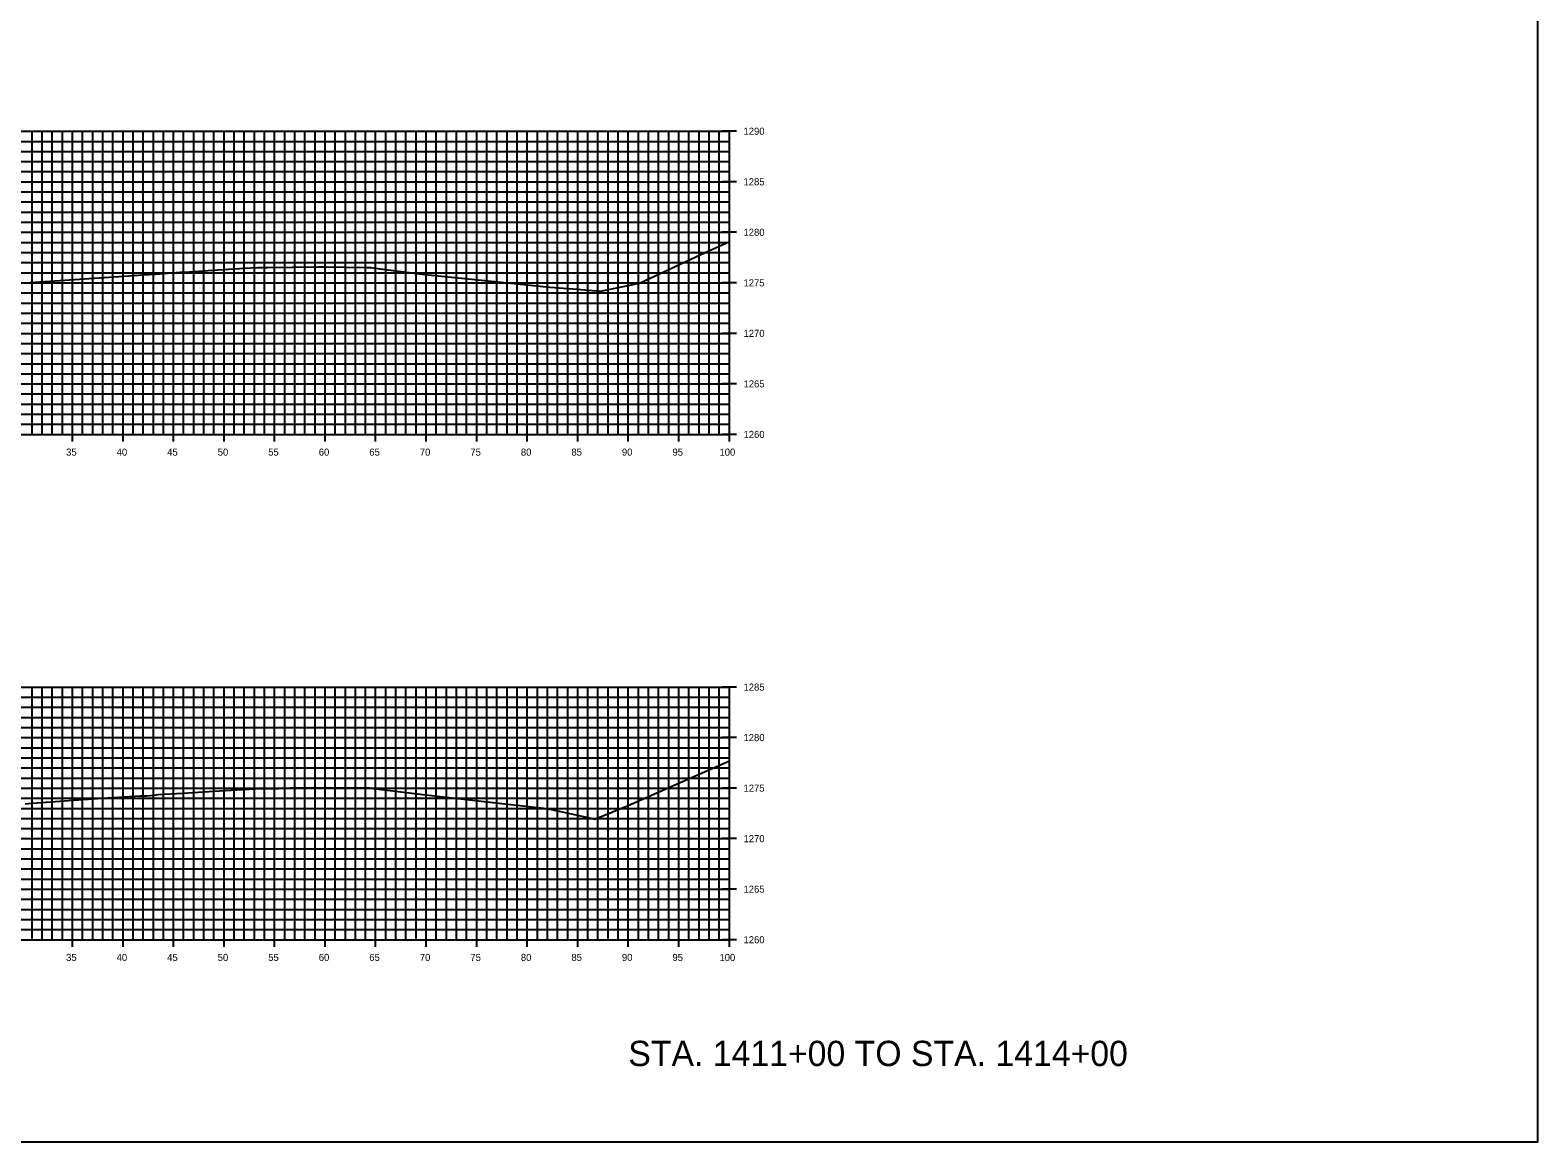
# Model space of a CAD drawing. Extents: x 674939 to 678919, y 750652 to 765176.
# Drawn here: x 678769.3 to 678918.5, y 757132.6 to 757242.6 of the extents above; entities that cross this region are included whole.
import ezdxf

# ---------------------------------------------------------------- set-up
doc = ezdxf.new("R2010")
doc.units = 0
for name, color, linetype in [('Level 10', 7, 'Continuous'), ('Level 20', 7, 'Continuous'), ('Level 21', 7, 'Continuous'), ('Level 4', 7, 'Continuous'), ('Level 8', 7, 'Continuous'), ('Level 9', 7, 'Continuous')]:
    doc.layers.add(name, color=color, linetype=linetype)

msp = doc.modelspace()

# ---------------------------------------------------------------- linework, layer by layer
at = {"layer": 'Level 10'}
for points in [[(678768.39, 757217.5), (678770.77, 757217.69), (678771.79, 757217.76), (678780.57, 757218.34), (678781.69, 757218.41), (678781.76, 757218.41), (678782.2, 757218.45), (678784.16, 757218.59), (678785.11, 757218.65), (678787.89, 757218.83), (678791.15, 757219.02), (678791.88, 757219.06), (678792.07, 757219.07), (678792.09, 757219.07), (678792.84, 757219.08), (678797.78, 757219.13), (678798.55, 757219.13), (678802.68, 757219.07), (678803.06, 757219.06), (678803.09, 757219.06), (678803.99, 757218.95), (678808.4, 757218.38), (678813.99, 757217.81), (678820.78, 757217.13), (678823.05, 757216.95), (678825.79, 757216.72), (678828.52, 757217.29), (678829.64, 757217.51), (678836.13, 757220.55), (678838.53, 757221.65)], [(678768.86, 757166.01), (678769.56, 757166.07), (678773.17, 757166.32), (678775.08, 757166.45), (678777, 757166.58), (678780.24, 757166.79), (678780.64, 757166.8), (678780.88, 757166.79), (678781.6, 757166.87), (678782, 757166.91), (678784.4, 757167.06), (678788.12, 757167.29), (678789.78, 757167.39), (678792.17, 757167.51), (678792.26, 757167.51), (678792.4, 757167.52), (678792.64, 757167.5), (678793.24, 757167.49), (678793.96, 757167.53), (678795.04, 757167.57), (678796.64, 757167.59), (678799.41, 757167.59), (678801, 757167.58), (678802.92, 757167.57), (678803, 757167.56), (678804.96, 757167.32), (678807.63, 757167), (678815.42, 757166.1), (678820.46, 757165.54), (678824.99, 757164.54), (678825.11, 757164.52), (678825.21, 757164.49), (678825.27, 757164.52), (678828.51, 757165.82), (678833.07, 757167.84), (678838.53, 757170.26)]]:
    msp.add_lwpolyline(points, dxfattribs=at)
at = {"layer": 'Level 20'}
for p, q in [((678638.53, 757232.55), (678838.53, 757232.55)), ((678769.53, 757202.55), (678769.53, 757232.55)), ((678770.53, 757202.55), (678770.53, 757232.55)), ((678771.53, 757202.55), (678771.53, 757232.55)), ((678772.53, 757202.55), (678772.53, 757232.55)), ((678773.53, 757202.55), (678773.53, 757232.55)), ((678774.53, 757202.55), (678774.53, 757232.55)), ((678775.53, 757202.55), (678775.53, 757232.55)), ((678776.53, 757202.55), (678776.53, 757232.55)), ((678777.53, 757202.55), (678777.53, 757232.55)), ((678778.53, 757202.55), (678778.53, 757232.55)), ((678779.53, 757202.55), (678779.53, 757232.55)), ((678780.53, 757202.55), (678780.53, 757232.55)), ((678781.53, 757202.55), (678781.53, 757232.55)), ((678782.53, 757202.55), (678782.53, 757232.55)), ((678783.53, 757202.55), (678783.53, 757232.55)), ((678784.53, 757202.55), (678784.53, 757232.55)), ((678785.53, 757202.55), (678785.53, 757232.55)), ((678786.53, 757202.55), (678786.53, 757232.55)), ((678787.53, 757202.55), (678787.53, 757232.55)), ((678788.53, 757202.55), (678788.53, 757232.55)), ((678789.53, 757202.55), (678789.53, 757232.55)), ((678790.53, 757202.55), (678790.53, 757232.55)), ((678791.53, 757202.55), (678791.53, 757232.55)), ((678792.53, 757202.55), (678792.53, 757232.55)), ((678793.53, 757202.55), (678793.53, 757232.55)), ((678794.53, 757202.55), (678794.53, 757232.55)), ((678795.53, 757202.55), (678795.53, 757232.55)), ((678796.53, 757202.55), (678796.53, 757232.55)), ((678797.53, 757202.55), (678797.53, 757232.55)), ((678798.53, 757202.55), (678798.53, 757232.55)), ((678799.53, 757202.55), (678799.53, 757232.55)), ((678800.53, 757202.55), (678800.53, 757232.55)), ((678801.53, 757202.55), (678801.53, 757232.55)), ((678802.53, 757202.55), (678802.53, 757232.55)), ((678803.53, 757202.55), (678803.53, 757232.55)), ((678804.53, 757202.55), (678804.53, 757232.55)), ((678805.53, 757202.55), (678805.53, 757232.55)), ((678806.53, 757202.55), (678806.53, 757232.55)), ((678807.53, 757202.55), (678807.53, 757232.55)), ((678808.53, 757202.55), (678808.53, 757232.55)), ((678809.53, 757202.55), (678809.53, 757232.55)), ((678810.53, 757202.55), (678810.53, 757232.55)), ((678811.53, 757202.55), (678811.53, 757232.55)), ((678812.53, 757202.55), (678812.53, 757232.55)), ((678813.53, 757202.55), (678813.53, 757232.55)), ((678814.53, 757202.55), (678814.53, 757232.55)), ((678815.53, 757202.55), (678815.53, 757232.55)), ((678816.53, 757202.55), (678816.53, 757232.55)), ((678817.53, 757202.55), (678817.53, 757232.55)), ((678818.53, 757202.55), (678818.53, 757232.55)), ((678819.53, 757202.55), (678819.53, 757232.55)), ((678820.53, 757202.55), (678820.53, 757232.55)), ((678821.53, 757202.55), (678821.53, 757232.55)), ((678822.53, 757202.55), (678822.53, 757232.55)), ((678823.53, 757202.55), (678823.53, 757232.55)), ((678824.53, 757202.55), (678824.53, 757232.55)), ((678825.53, 757202.55), (678825.53, 757232.55)), ((678826.53, 757202.55), (678826.53, 757232.55)), ((678827.53, 757202.55), (678827.53, 757232.55)), ((678828.53, 757202.55), (678828.53, 757232.55)), ((678829.53, 757202.55), (678829.53, 757232.55)), ((678830.53, 757202.55), (678830.53, 757232.55)), ((678831.53, 757202.55), (678831.53, 757232.55)), ((678832.53, 757202.55), (678832.53, 757232.55)), ((678833.53, 757202.55), (678833.53, 757232.55)), ((678834.53, 757202.55), (678834.53, 757232.55)), ((678835.53, 757202.55), (678835.53, 757232.55)), ((678836.53, 757202.55), (678836.53, 757232.55)), ((678837.53, 757202.55), (678837.53, 757232.55)), ((678838.53, 757202.55), (678838.53, 757232.55)), ((678638.53, 757231.55), (678838.53, 757231.55)), ((678638.53, 757230.55), (678838.53, 757230.55)), ((678638.53, 757229.55), (678838.53, 757229.55)), ((678638.53, 757228.55), (678838.53, 757228.55)), ((678638.53, 757227.55), (678838.53, 757227.55)), ((678638.53, 757226.55), (678838.53, 757226.55)), ((678638.53, 757225.55), (678838.53, 757225.55)), ((678638.53, 757224.55), (678838.53, 757224.55)), ((678638.53, 757223.55), (678838.53, 757223.55)), ((678638.53, 757222.55), (678838.53, 757222.55)), ((678638.53, 757221.55), (678838.53, 757221.55)), ((678638.53, 757220.55), (678838.53, 757220.55)), ((678638.53, 757219.55), (678838.53, 757219.55)), ((678638.53, 757218.55), (678838.53, 757218.55)), ((678638.53, 757217.55), (678838.53, 757217.55)), ((678638.53, 757216.55), (678838.53, 757216.55)), ((678638.53, 757215.55), (678838.53, 757215.55)), ((678638.53, 757214.55), (678838.53, 757214.55)), ((678638.53, 757213.55), (678838.53, 757213.55)), ((678638.53, 757212.55), (678838.53, 757212.55)), ((678638.53, 757211.55), (678838.53, 757211.55)), ((678638.53, 757210.55), (678838.53, 757210.55)), ((678638.53, 757209.55), (678838.53, 757209.55)), ((678638.53, 757208.55), (678838.53, 757208.55)), ((678638.53, 757207.55), (678838.53, 757207.55)), ((678638.53, 757206.55), (678838.53, 757206.55)), ((678638.53, 757205.55), (678838.53, 757205.55)), ((678638.53, 757204.55), (678838.53, 757204.55)), ((678638.53, 757203.55), (678838.53, 757203.55)), ((678638.53, 757202.55), (678838.53, 757202.55)), ((678638.53, 757177.55), (678838.53, 757177.55)), ((678769.53, 757152.55), (678769.53, 757177.55)), ((678770.53, 757152.55), (678770.53, 757177.55)), ((678771.53, 757152.55), (678771.53, 757177.55)), ((678772.53, 757152.55), (678772.53, 757177.55)), ((678773.53, 757152.55), (678773.53, 757177.55)), ((678774.53, 757152.55), (678774.53, 757177.55)), ((678775.53, 757152.55), (678775.53, 757177.55)), ((678776.53, 757152.55), (678776.53, 757177.55)), ((678777.53, 757152.55), (678777.53, 757177.55)), ((678778.53, 757152.55), (678778.53, 757177.55)), ((678779.53, 757152.55), (678779.53, 757177.55)), ((678780.53, 757152.55), (678780.53, 757177.55)), ((678781.53, 757152.55), (678781.53, 757177.55)), ((678782.53, 757152.55), (678782.53, 757177.55)), ((678783.53, 757152.55), (678783.53, 757177.55)), ((678784.53, 757152.55), (678784.53, 757177.55)), ((678785.53, 757152.55), (678785.53, 757177.55)), ((678786.53, 757152.55), (678786.53, 757177.55)), ((678787.53, 757152.55), (678787.53, 757177.55)), ((678788.53, 757152.55), (678788.53, 757177.55)), ((678789.53, 757152.55), (678789.53, 757177.55)), ((678790.53, 757152.55), (678790.53, 757177.55)), ((678791.53, 757152.55), (678791.53, 757177.55)), ((678792.53, 757152.55), (678792.53, 757177.55)), ((678793.53, 757152.55), (678793.53, 757177.55)), ((678794.53, 757152.55), (678794.53, 757177.55)), ((678795.53, 757152.55), (678795.53, 757177.55)), ((678796.53, 757152.55), (678796.53, 757177.55)), ((678797.53, 757152.55), (678797.53, 757177.55)), ((678798.53, 757152.55), (678798.53, 757177.55)), ((678799.53, 757152.55), (678799.53, 757177.55)), ((678800.53, 757152.55), (678800.53, 757177.55)), ((678801.53, 757152.55), (678801.53, 757177.55)), ((678802.53, 757152.55), (678802.53, 757177.55)), ((678803.53, 757152.55), (678803.53, 757177.55)), ((678804.53, 757152.55), (678804.53, 757177.55)), ((678805.53, 757152.55), (678805.53, 757177.55)), ((678806.53, 757152.55), (678806.53, 757177.55)), ((678807.53, 757152.55), (678807.53, 757177.55)), ((678808.53, 757152.55), (678808.53, 757177.55)), ((678809.53, 757152.55), (678809.53, 757177.55)), ((678810.53, 757152.55), (678810.53, 757177.55)), ((678811.53, 757152.55), (678811.53, 757177.55)), ((678812.53, 757152.55), (678812.53, 757177.55)), ((678813.53, 757152.55), (678813.53, 757177.55)), ((678814.53, 757152.55), (678814.53, 757177.55)), ((678815.53, 757152.55), (678815.53, 757177.55)), ((678816.53, 757152.55), (678816.53, 757177.55)), ((678817.53, 757152.55), (678817.53, 757177.55)), ((678818.53, 757152.55), (678818.53, 757177.55)), ((678819.53, 757152.55), (678819.53, 757177.55)), ((678820.53, 757152.55), (678820.53, 757177.55)), ((678821.53, 757152.55), (678821.53, 757177.55)), ((678822.53, 757152.55), (678822.53, 757177.55)), ((678823.53, 757152.55), (678823.53, 757177.55)), ((678824.53, 757152.55), (678824.53, 757177.55)), ((678825.53, 757152.55), (678825.53, 757177.55)), ((678826.53, 757152.55), (678826.53, 757177.55)), ((678827.53, 757152.55), (678827.53, 757177.55)), ((678828.53, 757152.55), (678828.53, 757177.55)), ((678829.53, 757152.55), (678829.53, 757177.55)), ((678830.53, 757152.55), (678830.53, 757177.55)), ((678831.53, 757152.55), (678831.53, 757177.55)), ((678832.53, 757152.55), (678832.53, 757177.55)), ((678833.53, 757152.55), (678833.53, 757177.55)), ((678834.53, 757152.55), (678834.53, 757177.55)), ((678835.53, 757152.55), (678835.53, 757177.55)), ((678836.53, 757152.55), (678836.53, 757177.55)), ((678837.53, 757152.55), (678837.53, 757177.55)), ((678838.53, 757152.55), (678838.53, 757177.55)), ((678638.53, 757176.55), (678838.53, 757176.55)), ((678638.53, 757175.55), (678838.53, 757175.55)), ((678638.53, 757174.55), (678838.53, 757174.55)), ((678638.53, 757173.55), (678838.53, 757173.55)), ((678638.53, 757172.55), (678838.53, 757172.55)), ((678638.53, 757171.55), (678838.53, 757171.55)), ((678638.53, 757170.55), (678838.53, 757170.55)), ((678638.53, 757169.55), (678838.53, 757169.55)), ((678638.53, 757168.55), (678838.53, 757168.55)), ((678638.53, 757167.55), (678838.53, 757167.55)), ((678638.53, 757166.55), (678838.53, 757166.55)), ((678638.53, 757165.55), (678838.53, 757165.55)), ((678638.53, 757164.55), (678838.53, 757164.55)), ((678638.53, 757163.55), (678838.53, 757163.55)), ((678638.53, 757162.55), (678838.53, 757162.55)), ((678638.53, 757161.55), (678838.53, 757161.55)), ((678638.53, 757160.55), (678838.53, 757160.55)), ((678638.53, 757159.55), (678838.53, 757159.55)), ((678638.53, 757158.55), (678838.53, 757158.55)), ((678638.53, 757157.55), (678838.53, 757157.55)), ((678638.53, 757156.55), (678838.53, 757156.55)), ((678638.53, 757155.55), (678838.53, 757155.55)), ((678638.53, 757154.55), (678838.53, 757154.55)), ((678638.53, 757153.55), (678838.53, 757153.55)), ((678638.53, 757152.55), (678838.53, 757152.55))]:
    msp.add_line(p, q, dxfattribs=at)
at = {"layer": 'Level 4'}
msp.add_lwpolyline([(678578.53, 757132.55), (678918.53, 757132.55), (678918.53, 757352.55), (678578.53, 757352.55)], close=True, dxfattribs=at)
at = {"layer": 'Level 8'}
for p, q in [((678839.23, 757232.55), (678837.83, 757232.55)), ((678838.53, 757202.55), (678838.53, 757232.55)), ((678839.23, 757227.55), (678837.83, 757227.55)), ((678839.23, 757222.55), (678837.83, 757222.55)), ((678839.23, 757217.55), (678837.83, 757217.55)), ((678839.23, 757212.55), (678837.83, 757212.55)), ((678839.23, 757207.55), (678837.83, 757207.55)), ((678638.53, 757202.55), (678838.53, 757202.55)), ((678773.53, 757201.85), (678773.53, 757203.25)), ((678778.53, 757201.85), (678778.53, 757203.25)), ((678783.53, 757201.85), (678783.53, 757203.25)), ((678788.53, 757201.85), (678788.53, 757203.25)), ((678793.53, 757201.85), (678793.53, 757203.25)), ((678798.53, 757201.85), (678798.53, 757203.25)), ((678803.53, 757201.85), (678803.53, 757203.25)), ((678808.53, 757201.85), (678808.53, 757203.25)), ((678813.53, 757201.85), (678813.53, 757203.25)), ((678818.53, 757201.85), (678818.53, 757203.25)), ((678823.53, 757201.85), (678823.53, 757203.25)), ((678828.53, 757201.85), (678828.53, 757203.25)), ((678833.53, 757201.85), (678833.53, 757203.25)), ((678839.23, 757202.55), (678837.83, 757202.55)), ((678838.53, 757201.85), (678838.53, 757203.25)), ((678839.23, 757177.55), (678837.83, 757177.55)), ((678838.53, 757152.55), (678838.53, 757177.55)), ((678839.23, 757172.55), (678837.83, 757172.55)), ((678839.23, 757167.55), (678837.83, 757167.55)), ((678839.23, 757162.55), (678837.83, 757162.55)), ((678839.23, 757157.55), (678837.83, 757157.55)), ((678773.53, 757151.85), (678773.53, 757153.25)), ((678778.53, 757151.85), (678778.53, 757153.25)), ((678783.53, 757151.85), (678783.53, 757153.25)), ((678788.53, 757151.85), (678788.53, 757153.25)), ((678793.53, 757151.85), (678793.53, 757153.25)), ((678798.53, 757151.85), (678798.53, 757153.25)), ((678803.53, 757151.85), (678803.53, 757153.25)), ((678808.53, 757151.85), (678808.53, 757153.25)), ((678813.53, 757151.85), (678813.53, 757153.25)), ((678818.53, 757151.85), (678818.53, 757153.25)), ((678823.53, 757151.85), (678823.53, 757153.25)), ((678828.53, 757151.85), (678828.53, 757153.25)), ((678833.53, 757151.85), (678833.53, 757153.25)), ((678838.53, 757151.85), (678838.53, 757153.25)), ((678638.53, 757152.55), (678838.53, 757152.55)), ((678839.23, 757152.55), (678837.83, 757152.55))]:
    msp.add_line(p, q, dxfattribs=at)

# ---------------------------------------------------------------- texts
at = {"layer": 'Level 21'}
msp.add_text('STA. 1411+00 TO STA. 1414+00', height=2.5, dxfattribs=at).set_placement((678828.53, 757140.05))
at = {"layer": 'Level 9'}
for s, p in [('1290', (678839.93, 757232.2)), ('1285', (678839.93, 757227.2)), ('1280', (678839.93, 757222.2)), ('1275', (678839.93, 757217.2)), ('1270', (678839.93, 757212.2)), ('1265', (678839.93, 757207.2)), ('1260', (678839.93, 757202.2)), ('35', (678772.9, 757200.45)), ('40', (678777.9, 757200.45)), ('45', (678782.9, 757200.45)), ('50', (678787.9, 757200.45)), ('55', (678792.9, 757200.45)), ('60', (678797.9, 757200.45)), ('65', (678802.9, 757200.45)), ('70', (678807.9, 757200.45)), ('75', (678812.9, 757200.45)), ('80', (678817.9, 757200.45)), ('85', (678822.9, 757200.45)), ('90', (678827.9, 757200.45)), ('95', (678832.9, 757200.45)), ('100', (678837.55, 757200.45)), ('1285', (678839.93, 757177.2)), ('1280', (678839.93, 757172.2)), ('1275', (678839.93, 757167.2)), ('1270', (678839.93, 757162.2)), ('1265', (678839.93, 757157.2)), ('1260', (678839.93, 757152.2)), ('35', (678772.9, 757150.45)), ('40', (678777.9, 757150.45)), ('45', (678782.9, 757150.45)), ('50', (678787.9, 757150.45)), ('55', (678792.9, 757150.45)), ('60', (678797.9, 757150.45)), ('65', (678802.9, 757150.45)), ('70', (678807.9, 757150.45)), ('75', (678812.9, 757150.45)), ('80', (678817.9, 757150.45)), ('85', (678822.9, 757150.45)), ('90', (678827.9, 757150.45)), ('95', (678832.9, 757150.45)), ('100', (678837.55, 757150.45))]:
    msp.add_text(s, height=0.7, dxfattribs=at).set_placement(p)

doc.saveas('drawing.dxf')
